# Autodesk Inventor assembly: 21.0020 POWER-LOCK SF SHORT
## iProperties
Created: 2012-06
Part Number: 21.0020 POWER-LOCK SF SHORT
Document SubType Name: Assembly
Designer: Administrator
Mass: 26.8346 g
Surface Area: 33.3713 cm^2
Volume: 3.41572 cm^3
Density: 7.8562 g/cm^3
Author: Administrator
